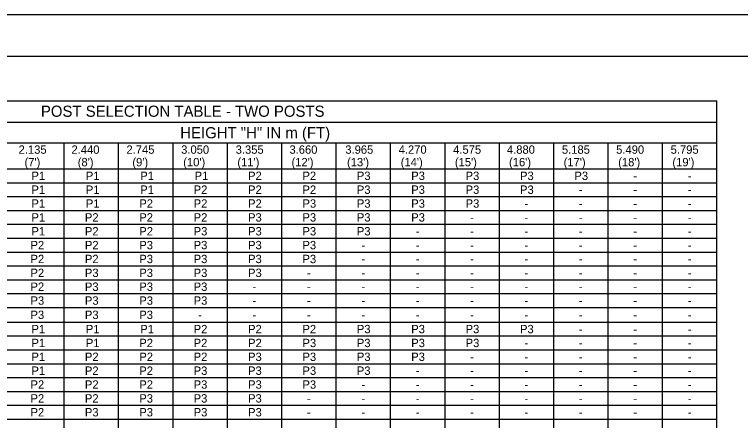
# Model space of a CAD drawing. Extents: x 637580 to 641008, y 294594 to 295782.
# Drawn here: x 638624.8 to 638885.2, y 295636 to 295781.6 of the extents above; entities that cross this region are included whole.
import ezdxf

# ---------------------------------------------------------------- set-up
doc = ezdxf.new("R2010")
doc.units = 0
for name, color, linetype in [('1', 7, 'Continuous'), ('2', 7, 'Continuous'), ('PLT-BNDY', 7, 'Continuous')]:
    doc.layers.add(name, color=color, linetype=linetype)

msp = doc.modelspace()

# ---------------------------------------------------------------- linework, layer by layer
at = {"layer": '1'}
for p, q in [((638461.31, 295766.63), (639247.31, 295766.63)), ((638509.81, 295750.63), (638876.73, 295750.63)), ((638876.73, 295231.34), (638876.73, 295750.63)), ((638509.81, 295742.95), (638876.73, 295742.95)), ((638642.64, 295231.34), (638642.64, 295735.61)), ((638662.15, 295231.34), (638662.15, 295735.61)), ((638681.66, 295231.34), (638681.66, 295735.61)), ((638701.17, 295231.34), (638701.17, 295735.61)), ((638720.67, 295231.34), (638720.67, 295735.61)), ((638740.18, 295231.34), (638740.18, 295735.61)), ((638759.69, 295231.34), (638759.69, 295735.61)), ((638779.2, 295231.34), (638779.2, 295735.61)), ((638798.7, 295231.34), (638798.7, 295735.61)), ((638818.21, 295231.34), (638818.21, 295735.61)), ((638837.72, 295231.34), (638837.72, 295735.61)), ((638857.23, 295231.34), (638857.23, 295735.61)), ((638509.81, 295726.25), (638876.73, 295726.25)), ((638509.81, 295671.26), (638876.73, 295671.26))]:
    msp.add_line(p, q, dxfattribs=at)
at = {"layer": '2'}
for p, q in [((638564.61, 295735.61), (638876.73, 295735.61)), ((638536.61, 295721.27), (638876.73, 295721.27)), ((638536.61, 295716.3), (638876.73, 295716.3)), ((638536.61, 295711.33), (638876.73, 295711.33)), ((638536.61, 295706.36), (638876.73, 295706.36)), ((638536.61, 295701.39), (638876.73, 295701.39)), ((638536.61, 295696.41), (638876.73, 295696.41)), ((638536.61, 295691.44), (638876.73, 295691.44)), ((638536.61, 295686.47), (638876.73, 295686.47)), ((638536.61, 295681.5), (638876.73, 295681.5)), ((638536.61, 295676.52), (638876.73, 295676.52)), ((638536.61, 295666.29), (638876.73, 295666.29)), ((638536.61, 295661.31), (638876.73, 295661.31)), ((638536.61, 295656.34), (638876.73, 295656.34)), ((638536.61, 295651.37), (638876.73, 295651.37)), ((638536.61, 295646.4), (638876.73, 295646.4)), ((638536.61, 295641.42), (638876.73, 295641.42)), ((638536.61, 295636.45), (638876.73, 295636.45))]:
    msp.add_line(p, q, dxfattribs=at)
at = {"layer": 'PLT-BNDY'}
msp.add_lwpolyline([(638421.31, 295781.63), (639262.31, 295781.63), (639262.31, 295187.63), (638421.31, 295187.63)], close=True, dxfattribs=at)

# ---------------------------------------------------------------- texts
at = {"layer": '1'}
for s, height, p in [('POST SELECTION TABLE - TWO POSTS', 4.003, (638634.27, 295744.93)), ('HEIGHT "H" IN m (FT)', 4.003, (638684.25, 295737.21)), ('2.135', 3, (638626.27, 295731.67)), ('2.440', 3, (638645.24, 295731.67)), ('2.745', 3, (638664.95, 295731.67)), ('3.050', 3, (638684.57, 295731.67)), ('3.355', 3, (638704.12, 295731.67)), ('3.660', 3, (638723.41, 295731.67)), ('3.965', 3, (638743.44, 295731.67)), ('4.270', 3, (638762.57, 295731.67)), ('4.575', 3, (638782.12, 295731.67)), ('4.880', 3, (638801.41, 295731.67)), ('5.185', 3, (638821.13, 295731.67)), ('5.490', 3, (638840.58, 295731.67)), ('5.795', 3, (638860.13, 295731.67)), ("(7')", 3, (638628.39, 295727.17)), ("(8')", 3, (638647.48, 295727.17)), ("(9')", 3, (638667.07, 295727.17)), ("(10')", 3, (638685.31, 295727.17)), ("(11')", 3, (638704.73, 295727.17)), ("(12')", 3, (638724.15, 295727.17)), ("(13')", 3, (638744.06, 295727.17)), ("(14')", 3, (638763.32, 295727.17)), ("(15')", 3, (638782.74, 295727.17)), ("(16')", 3, (638802.16, 295727.17)), ("(17')", 3, (638821.74, 295727.17)), ("(18')", 3, (638841.32, 295727.17)), ("(19')", 3, (638860.75, 295727.17)), ('P1', 3, (638630.88, 295722.26)), ('P1', 3, (638650.39, 295722.26)), ('P1', 3, (638669.9, 295722.26)), ('P1', 3, (638689.41, 295722.26)), ('P2', 3, (638708.57, 295722.26)), ('P2', 3, (638728.08, 295722.26)), ('P3', 3, (638747.59, 295722.26)), ('P3', 3, (638767.09, 295722.26)), ('P3', 3, (638786.6, 295722.26)), ('P3', 3, (638806.11, 295722.26)), ('P3', 3, (638825.62, 295722.26)), ('-', 3, (638846.74, 295722.26)), ('-', 3, (638866.25, 295722.26)), ('P1', 3, (638630.88, 295717.29)), ('P1', 3, (638650.39, 295717.29)), ('P1', 3, (638669.9, 295717.29)), ('P2', 3, (638689.06, 295717.29)), ('P2', 3, (638708.57, 295717.29)), ('P2', 3, (638728.08, 295717.29)), ('P3', 3, (638747.59, 295717.29)), ('P3', 3, (638767.09, 295717.29)), ('P3', 3, (638786.6, 295717.29)), ('P3', 3, (638806.11, 295717.29)), ('-', 3, (638827.23, 295717.29)), ('-', 3, (638846.74, 295717.29)), ('-', 3, (638866.25, 295717.29)), ('P1', 3, (638630.88, 295712.32)), ('P1', 3, (638650.39, 295712.32)), ('P2', 3, (638669.56, 295712.32)), ('P2', 3, (638689.06, 295712.32)), ('P2', 3, (638708.57, 295712.32)), ('P3', 3, (638728.08, 295712.32)), ('P3', 3, (638747.59, 295712.32)), ('P3', 3, (638767.09, 295712.32)), ('P3', 3, (638786.6, 295712.32)), ('-', 3, (638807.73, 295712.32)), ('-', 3, (638827.23, 295712.32)), ('-', 3, (638846.74, 295712.32)), ('-', 3, (638866.25, 295712.32)), ('P1', 3, (638630.88, 295707.34)), ('P2', 3, (638650.05, 295707.34)), ('P2', 3, (638669.56, 295707.34)), ('P2', 3, (638689.06, 295707.34)), ('P3', 3, (638708.57, 295707.34)), ('P3', 3, (638728.08, 295707.34)), ('P3', 3, (638747.59, 295707.34)), ('P3', 3, (638767.09, 295707.34)), ('-', 3, (638788.22, 295707.34)), ('-', 3, (638807.73, 295707.34)), ('-', 3, (638827.23, 295707.34)), ('-', 3, (638846.74, 295707.34)), ('-', 3, (638866.25, 295707.34)), ('P1', 3, (638630.88, 295702.37)), ('P2', 3, (638650.05, 295702.37)), ('P2', 3, (638669.56, 295702.37)), ('P3', 3, (638689.06, 295702.37)), ('P3', 3, (638708.57, 295702.37)), ('P3', 3, (638728.08, 295702.37)), ('P3', 3, (638747.59, 295702.37)), ('-', 3, (638768.71, 295702.37)), ('-', 3, (638788.22, 295702.37)), ('-', 3, (638807.73, 295702.37)), ('-', 3, (638827.23, 295702.37)), ('-', 3, (638846.74, 295702.37)), ('-', 3, (638866.25, 295702.37)), ('P2', 3, (638630.54, 295697.4)), ('P2', 3, (638650.05, 295697.4)), ('P3', 3, (638669.56, 295697.4)), ('P3', 3, (638689.06, 295697.4)), ('P3', 3, (638708.57, 295697.4)), ('P3', 3, (638728.08, 295697.4)), ('-', 3, (638749.2, 295697.4)), ('-', 3, (638768.71, 295697.4)), ('-', 3, (638788.22, 295697.4)), ('-', 3, (638807.73, 295697.4)), ('-', 3, (638827.23, 295697.4)), ('-', 3, (638846.74, 295697.4)), ('-', 3, (638866.25, 295697.4)), ('P2', 3, (638630.54, 295692.43)), ('P2', 3, (638650.05, 295692.43)), ('P3', 3, (638669.56, 295692.43)), ('P3', 3, (638689.06, 295692.43)), ('P3', 3, (638708.57, 295692.43)), ('P3', 3, (638728.08, 295692.43)), ('-', 3, (638749.2, 295692.43)), ('-', 3, (638768.71, 295692.43)), ('-', 3, (638788.22, 295692.43)), ('-', 3, (638807.73, 295692.43)), ('-', 3, (638827.23, 295692.43)), ('-', 3, (638846.74, 295692.43)), ('-', 3, (638866.25, 295692.43)), ('P2', 3, (638630.54, 295687.45)), ('P3', 3, (638650.05, 295687.45)), ('P3', 3, (638669.56, 295687.45)), ('P3', 3, (638689.06, 295687.45)), ('P3', 3, (638708.57, 295687.45)), ('-', 3, (638729.7, 295687.45)), ('-', 3, (638749.2, 295687.45)), ('-', 3, (638768.71, 295687.45)), ('-', 3, (638788.22, 295687.45)), ('-', 3, (638807.73, 295687.45)), ('-', 3, (638827.23, 295687.45)), ('-', 3, (638846.74, 295687.45)), ('-', 3, (638866.25, 295687.45)), ('P2', 3, (638630.54, 295682.48)), ('P3', 3, (638650.05, 295682.48)), ('P3', 3, (638669.56, 295682.48)), ('P3', 3, (638689.06, 295682.48)), ('-', 3, (638710.19, 295682.48)), ('-', 3, (638729.7, 295682.48)), ('-', 3, (638749.2, 295682.48)), ('-', 3, (638768.71, 295682.48)), ('-', 3, (638788.22, 295682.48)), ('-', 3, (638807.73, 295682.48)), ('-', 3, (638827.23, 295682.48)), ('-', 3, (638846.74, 295682.48)), ('-', 3, (638866.25, 295682.48)), ('P3', 3, (638630.54, 295677.51)), ('P3', 3, (638650.05, 295677.51)), ('P3', 3, (638669.56, 295677.51)), ('P3', 3, (638689.06, 295677.51)), ('-', 3, (638710.19, 295677.51)), ('-', 3, (638729.7, 295677.51)), ('-', 3, (638749.2, 295677.51)), ('-', 3, (638768.71, 295677.51)), ('-', 3, (638788.22, 295677.51)), ('-', 3, (638807.73, 295677.51)), ('-', 3, (638827.23, 295677.51)), ('-', 3, (638846.74, 295677.51)), ('-', 3, (638866.25, 295677.51)), ('P3', 3, (638630.54, 295672.39)), ('P3', 3, (638650.05, 295672.39)), ('P3', 3, (638669.56, 295672.39)), ('-', 3, (638690.68, 295672.39)), ('-', 3, (638710.19, 295672.39)), ('-', 3, (638729.7, 295672.39)), ('-', 3, (638749.2, 295672.39)), ('-', 3, (638768.71, 295672.39)), ('-', 3, (638788.22, 295672.39)), ('-', 3, (638807.73, 295672.39)), ('-', 3, (638827.23, 295672.39)), ('-', 3, (638846.74, 295672.39)), ('-', 3, (638866.25, 295672.39)), ('P1', 3, (638630.88, 295667.27)), ('P1', 3, (638650.39, 295667.27)), ('P1', 3, (638669.9, 295667.27)), ('P2', 3, (638689.06, 295667.27)), ('P2', 3, (638708.57, 295667.27)), ('P2', 3, (638728.08, 295667.27)), ('P3', 3, (638747.59, 295667.27)), ('P3', 3, (638767.09, 295667.27)), ('P3', 3, (638786.6, 295667.27)), ('P3', 3, (638806.11, 295667.27)), ('-', 3, (638827.23, 295667.27)), ('-', 3, (638846.74, 295667.27)), ('-', 3, (638866.25, 295667.27)), ('P2', 3, (638669.56, 295662.3)), ('P2', 3, (638689.06, 295662.3)), ('P2', 3, (638708.57, 295662.3)), ('P3', 3, (638728.08, 295662.3)), ('P3', 3, (638747.59, 295662.3)), ('P3', 3, (638767.09, 295662.3)), ('P3', 3, (638786.6, 295662.3)), ('P1', 3, (638630.88, 295662.3)), ('P1', 3, (638650.39, 295662.3)), ('-', 3, (638807.73, 295662.3)), ('-', 3, (638827.23, 295662.3)), ('-', 3, (638846.74, 295662.3)), ('-', 3, (638866.25, 295662.3)), ('P1', 3, (638630.88, 295657.33)), ('P2', 3, (638650.05, 295657.33)), ('P2', 3, (638669.56, 295657.33)), ('P2', 3, (638689.06, 295657.33)), ('P3', 3, (638708.57, 295657.33)), ('P3', 3, (638728.08, 295657.33)), ('P3', 3, (638747.59, 295657.33)), ('P3', 3, (638767.09, 295657.33)), ('-', 3, (638788.22, 295657.33)), ('-', 3, (638807.73, 295657.33)), ('-', 3, (638827.23, 295657.33)), ('-', 3, (638846.74, 295657.33)), ('-', 3, (638866.25, 295657.33)), ('P1', 3, (638630.88, 295652.35)), ('P2', 3, (638650.05, 295652.35)), ('P2', 3, (638669.56, 295652.35)), ('P3', 3, (638689.06, 295652.35)), ('P3', 3, (638708.57, 295652.35)), ('P3', 3, (638728.08, 295652.35)), ('P3', 3, (638747.59, 295652.35)), ('-', 3, (638768.71, 295652.35)), ('-', 3, (638788.22, 295652.35)), ('-', 3, (638807.73, 295652.35)), ('-', 3, (638827.23, 295652.35)), ('-', 3, (638846.74, 295652.35)), ('-', 3, (638866.25, 295652.35)), ('P2', 3, (638630.54, 295647.38)), ('P2', 3, (638650.05, 295647.38)), ('P2', 3, (638669.56, 295647.38)), ('P3', 3, (638689.06, 295647.38)), ('P3', 3, (638708.57, 295647.38)), ('P3', 3, (638728.08, 295647.38)), ('-', 3, (638749.2, 295647.38)), ('-', 3, (638768.71, 295647.38)), ('-', 3, (638788.22, 295647.38)), ('-', 3, (638807.73, 295647.38)), ('-', 3, (638827.23, 295647.38)), ('-', 3, (638846.74, 295647.38)), ('-', 3, (638866.25, 295647.38)), ('P2', 3, (638630.54, 295642.41)), ('P2', 3, (638650.05, 295642.41)), ('P3', 3, (638669.56, 295642.41)), ('P3', 3, (638689.06, 295642.41)), ('P3', 3, (638708.57, 295642.41)), ('-', 3, (638729.7, 295642.41)), ('-', 3, (638749.2, 295642.41)), ('-', 3, (638768.71, 295642.41)), ('-', 3, (638788.22, 295642.41)), ('-', 3, (638807.73, 295642.41)), ('-', 3, (638827.23, 295642.41)), ('-', 3, (638846.74, 295642.41)), ('-', 3, (638866.25, 295642.41)), ('P2', 3, (638630.54, 295637.44)), ('P3', 3, (638650.05, 295637.44)), ('P3', 3, (638669.56, 295637.44)), ('P3', 3, (638689.06, 295637.44)), ('P3', 3, (638708.57, 295637.44)), ('-', 3, (638729.7, 295637.44)), ('-', 3, (638749.2, 295637.44)), ('-', 3, (638768.71, 295637.44)), ('-', 3, (638788.22, 295637.44)), ('-', 3, (638807.73, 295637.44)), ('-', 3, (638827.23, 295637.44)), ('-', 3, (638846.74, 295637.44)), ('-', 3, (638866.25, 295637.44))]:
    msp.add_text(s, height=height, dxfattribs=at).set_placement(p)

doc.saveas('drawing.dxf')
